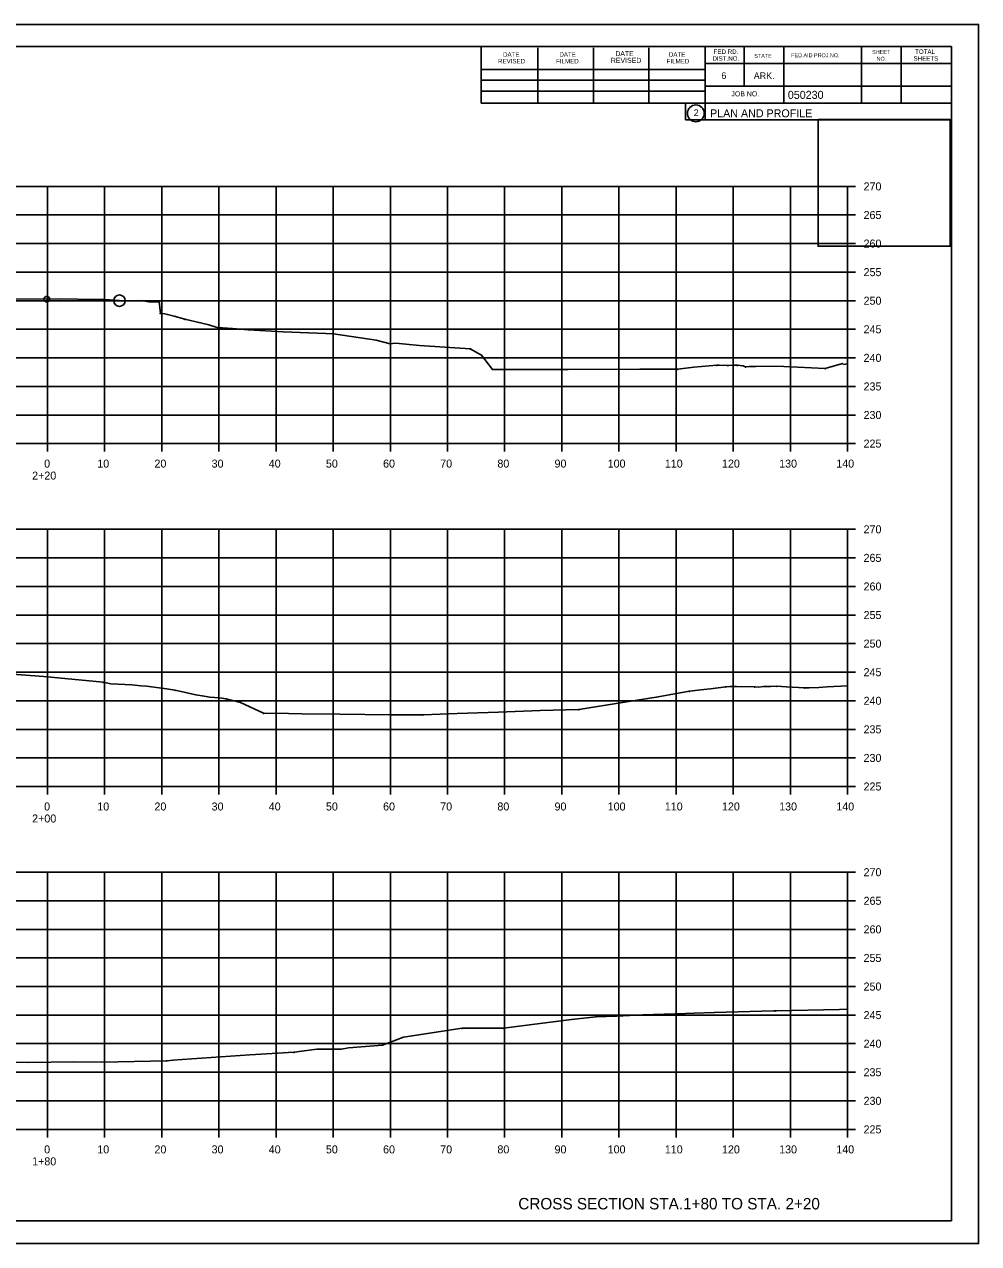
# Model space of a CAD drawing. Extents: x 1300404 to 1323571, y 234004 to 252077.
# Drawn here: x 1315713.3 to 1315880.2, y 240635.1 to 240848.4 of the extents above; entities that cross this region are included whole.
import ezdxf

# ---------------------------------------------------------------- set-up
doc = ezdxf.new("R2010")
doc.units = 0
for name, color, linetype in [('Default', 7, 'Continuous'), ('R_Axis', 7, 'Continuous'), ('R_Axis Annot', 7, 'Continuous'), ('R_Border', 7, 'Continuous'), ('R_Border Prem', 7, 'Continuous'), ('R_Draft', 7, 'Continuous'), ('R_Exist Surface', 7, 'Continuous'), ('R_Grid', 7, 'Continuous'), ('R_No Plot', 7, 'Continuous')]:
    doc.layers.add(name, color=color, linetype=linetype)

msp = doc.modelspace()

# ---------------------------------------------------------------- linework, layer by layer
at = {"layer": 'Default'}
for p, q in [((1315559.28, 240844.54), (1315875.46, 240844.54)), ((1315793.2, 240834.66), (1315793.2, 240844.54)), ((1315803.06, 240834.66), (1315803.06, 240844.34)), ((1315812.82, 240834.66), (1315812.82, 240844.34)), ((1315822.5, 240834.66), (1315822.5, 240844.34)), ((1315832.36, 240844.54), (1315832.36, 240831.74)), ((1315839.2, 240844.54), (1315839.2, 240837.6)), ((1315846.14, 240844.54), (1315846.14, 240834.66)), ((1315859.72, 240844.54), (1315859.72, 240834.66)), ((1315866.66, 240844.54), (1315866.66, 240834.66)), ((1315875.46, 240639.08), (1315875.46, 240844.54)), ((1315875.46, 240841.6), (1315832.36, 240841.6)), ((1315875.46, 240841.62), (1315875.46, 240841.62)), ((1315793.2, 240840.52), (1315832.36, 240840.52)), ((1315793.2, 240838.66), (1315832.36, 240838.66)), ((1315875.46, 240837.6), (1315832.36, 240837.6)), ((1315835.32, 240837.6), (1315875.46, 240837.6)), ((1315793.2, 240834.66), (1315793.2, 240836.72)), ((1315793.2, 240836.72), (1315832.36, 240836.72)), ((1315875.46, 240834.66), (1315793.2, 240834.66)), ((1315832.36, 240831.74), (1315875.46, 240831.74)), ((1315875.46, 240639.08), (1315559.28, 240639.08))]:
    msp.add_line(p, q, dxfattribs=at)
msp.add_circle((1315830.74, 240832.87), 1.47, dxfattribs=at)
at = {"layer": 'R_Axis'}
for p, q in [((1315857.28, 240775.08), (1315857.28, 240820.08)), ((1315858.68, 240820.08), (1315857.28, 240820.08)), ((1315858.68, 240815.08), (1315857.28, 240815.08)), ((1315858.68, 240810.08), (1315857.28, 240810.08)), ((1315858.68, 240805.08), (1315857.28, 240805.08)), ((1315858.68, 240800.08), (1315857.28, 240800.08)), ((1315858.68, 240795.08), (1315857.28, 240795.08)), ((1315858.68, 240790.08), (1315857.28, 240790.08)), ((1315858.68, 240785.08), (1315857.28, 240785.08)), ((1315858.68, 240780.08), (1315857.28, 240780.08)), ((1315577.28, 240775.08), (1315857.28, 240775.08)), ((1315717.28, 240773.68), (1315717.28, 240775.08)), ((1315727.28, 240773.68), (1315727.28, 240775.08)), ((1315737.28, 240773.68), (1315737.28, 240775.08)), ((1315747.28, 240773.68), (1315747.28, 240775.08)), ((1315757.28, 240773.68), (1315757.28, 240775.08)), ((1315767.28, 240773.68), (1315767.28, 240775.08)), ((1315777.28, 240773.68), (1315777.28, 240775.08)), ((1315787.28, 240773.68), (1315787.28, 240775.08)), ((1315797.28, 240773.68), (1315797.28, 240775.08)), ((1315807.28, 240773.68), (1315807.28, 240775.08)), ((1315817.28, 240773.68), (1315817.28, 240775.08)), ((1315827.28, 240773.68), (1315827.28, 240775.08)), ((1315837.28, 240773.68), (1315837.28, 240775.08)), ((1315847.28, 240773.68), (1315847.28, 240775.08)), ((1315857.28, 240773.68), (1315857.28, 240775.08)), ((1315858.68, 240775.08), (1315857.28, 240775.08)), ((1315857.28, 240715.08), (1315857.28, 240760.08)), ((1315858.68, 240760.08), (1315857.28, 240760.08)), ((1315858.68, 240755.08), (1315857.28, 240755.08)), ((1315858.68, 240750.08), (1315857.28, 240750.08)), ((1315858.68, 240745.08), (1315857.28, 240745.08)), ((1315858.68, 240740.08), (1315857.28, 240740.08)), ((1315858.68, 240735.08), (1315857.28, 240735.08)), ((1315858.68, 240730.08), (1315857.28, 240730.08)), ((1315858.68, 240725.08), (1315857.28, 240725.08)), ((1315858.68, 240720.08), (1315857.28, 240720.08)), ((1315577.28, 240715.08), (1315857.28, 240715.08)), ((1315717.28, 240713.68), (1315717.28, 240715.08)), ((1315727.28, 240713.68), (1315727.28, 240715.08)), ((1315737.28, 240713.68), (1315737.28, 240715.08)), ((1315747.28, 240713.68), (1315747.28, 240715.08)), ((1315757.28, 240713.68), (1315757.28, 240715.08)), ((1315767.28, 240713.68), (1315767.28, 240715.08)), ((1315777.28, 240713.68), (1315777.28, 240715.08)), ((1315787.28, 240713.68), (1315787.28, 240715.08)), ((1315797.28, 240713.68), (1315797.28, 240715.08)), ((1315807.28, 240713.68), (1315807.28, 240715.08)), ((1315817.28, 240713.68), (1315817.28, 240715.08)), ((1315827.28, 240713.68), (1315827.28, 240715.08)), ((1315837.28, 240713.68), (1315837.28, 240715.08)), ((1315847.28, 240713.68), (1315847.28, 240715.08)), ((1315857.28, 240713.68), (1315857.28, 240715.08)), ((1315858.68, 240715.08), (1315857.28, 240715.08)), ((1315857.28, 240655.08), (1315857.28, 240700.08)), ((1315858.68, 240700.08), (1315857.28, 240700.08)), ((1315858.68, 240695.08), (1315857.28, 240695.08)), ((1315858.68, 240690.08), (1315857.28, 240690.08)), ((1315858.68, 240685.08), (1315857.28, 240685.08)), ((1315858.68, 240680.08), (1315857.28, 240680.08)), ((1315858.68, 240675.08), (1315857.28, 240675.08)), ((1315858.68, 240670.08), (1315857.28, 240670.08)), ((1315858.68, 240665.08), (1315857.28, 240665.08)), ((1315858.68, 240660.08), (1315857.28, 240660.08)), ((1315577.28, 240655.08), (1315857.28, 240655.08)), ((1315717.28, 240653.68), (1315717.28, 240655.08)), ((1315727.28, 240653.68), (1315727.28, 240655.08)), ((1315737.28, 240653.68), (1315737.28, 240655.08)), ((1315747.28, 240653.68), (1315747.28, 240655.08)), ((1315757.28, 240653.68), (1315757.28, 240655.08)), ((1315767.28, 240653.68), (1315767.28, 240655.08)), ((1315777.28, 240653.68), (1315777.28, 240655.08)), ((1315787.28, 240653.68), (1315787.28, 240655.08)), ((1315797.28, 240653.68), (1315797.28, 240655.08)), ((1315807.28, 240653.68), (1315807.28, 240655.08)), ((1315817.28, 240653.68), (1315817.28, 240655.08)), ((1315827.28, 240653.68), (1315827.28, 240655.08)), ((1315837.28, 240653.68), (1315837.28, 240655.08)), ((1315847.28, 240653.68), (1315847.28, 240655.08)), ((1315857.28, 240653.68), (1315857.28, 240655.08)), ((1315858.68, 240655.08), (1315857.28, 240655.08))]:
    msp.add_line(p, q, dxfattribs=at)
at = {"layer": 'R_Draft'}
for points in [[(1315736.86, 240799.94), (1315736.91, 240799.84), (1315736.81, 240799.84)], [(1315737.04, 240797.94), (1315737.09, 240797.84), (1315736.99, 240797.84)], [(1315741.32, 240796.89), (1315741.37, 240796.79), (1315741.27, 240796.79)], [(1315747.17, 240795.4), (1315747.22, 240795.3), (1315747.12, 240795.3)], [(1315777.24, 240792.6), (1315777.29, 240792.5), (1315777.19, 240792.5)], [(1315791.24, 240791.71), (1315791.29, 240791.61), (1315791.19, 240791.61)], [(1315795.17, 240788.12), (1315795.22, 240788.02), (1315795.12, 240788.02)], [(1315827.59, 240788.15), (1315827.64, 240788.05), (1315827.54, 240788.05)], [(1315834.38, 240788.84), (1315834.43, 240788.74), (1315834.33, 240788.74)], [(1315836.34, 240788.79), (1315836.39, 240788.69), (1315836.29, 240788.69)], [(1315838.01, 240788.84), (1315838.06, 240788.74), (1315837.96, 240788.74)], [(1315839.43, 240788.57), (1315839.48, 240788.47), (1315839.38, 240788.47)], [(1315853.38, 240788.27), (1315853.43, 240788.17), (1315853.33, 240788.17)], [(1315727.06, 240733.36), (1315727.11, 240733.26), (1315727.01, 240733.26)], [(1315835.97, 240732.57), (1315836.02, 240732.47), (1315835.92, 240732.47)], [(1315840.99, 240732.57), (1315841.04, 240732.47), (1315840.94, 240732.47)], [(1315844.88, 240732.68), (1315844.93, 240732.58), (1315844.83, 240732.58)], [(1315849.72, 240732.4), (1315849.77, 240732.3), (1315849.67, 240732.3)], [(1315739.61, 240732), (1315739.66, 240731.9), (1315739.56, 240731.9)], [(1315748.56, 240730.47), (1315748.61, 240730.37), (1315748.51, 240730.37)], [(1315829.62, 240731.82), (1315829.67, 240731.72), (1315829.57, 240731.72)], [(1315810.28, 240728.61), (1315810.33, 240728.51), (1315810.23, 240728.51)], [(1315755.09, 240727.97), (1315755.14, 240727.87), (1315755.04, 240727.87)], [(1315783, 240727.66), (1315783.05, 240727.56), (1315782.95, 240727.56)], [(1315813.23, 240674.85), (1315813.28, 240674.75), (1315813.18, 240674.75)], [(1315833.98, 240675.61), (1315834.03, 240675.51), (1315833.93, 240675.51)], [(1315844.72, 240675.87), (1315844.77, 240675.77), (1315844.67, 240675.77)], [(1315789.82, 240672.82), (1315789.87, 240672.72), (1315789.77, 240672.72)], [(1315797.1, 240672.86), (1315797.15, 240672.76), (1315797.05, 240672.76)], [(1315760.44, 240668.63), (1315760.49, 240668.53), (1315760.39, 240668.53)], [(1315738.15, 240667.13), (1315738.2, 240667.03), (1315738.1, 240667.03)]]:
    msp.add_lwpolyline(points, close=True, dxfattribs=at)
at = {"layer": 'R_Exist Surface'}
for points in [[(1315711.59, 240800.38), (1315717.17, 240800.33), (1315719.63, 240800.41), (1315725.48, 240800.31), (1315727.26, 240800.27), (1315729.88, 240800.09), (1315730.83, 240800.05), (1315730.89, 240800.05), (1315731.2, 240800.05), (1315733.66, 240800.09), (1315735, 240799.9), (1315736.23, 240799.9), (1315736.43, 240799.9), (1315736.86, 240799.89), (1315736.99, 240798.37), (1315737.04, 240797.89), (1315737.83, 240797.76), (1315739.48, 240797.38), (1315741.32, 240796.84), (1315745.54, 240795.84), (1315747.17, 240795.35), (1315747.93, 240795.33), (1315749.67, 240795.24), (1315752.42, 240794.96), (1315758.55, 240794.66), (1315766.01, 240794.34), (1315767.36, 240794.3), (1315774.83, 240793.19), (1315777.24, 240792.55), (1315778.09, 240792.65), (1315778.85, 240792.6), (1315780.02, 240792.5), (1315782.41, 240792.27), (1315791.24, 240791.66), (1315793.25, 240790.56), (1315795.17, 240788.07), (1315803.81, 240788.02), (1315808.37, 240788.03), (1315820.92, 240788.08), (1315824.99, 240788.08), (1315827.59, 240788.1), (1315830.36, 240788.48), (1315834.38, 240788.79), (1315834.83, 240788.79), (1315836.34, 240788.74), (1315837.48, 240788.8), (1315838.01, 240788.79), (1315838.97, 240788.68), (1315839.43, 240788.52), (1315840.04, 240788.57), (1315841.21, 240788.58), (1315843.87, 240788.6), (1315846.11, 240788.54), (1315848.59, 240788.44), (1315853.38, 240788.22), (1315856.37, 240789.12), (1315856.58, 240788.93), (1315857.28, 240789.02)], [(1315707.92, 240734.96), (1315716.68, 240734.32), (1315727.06, 240733.31), (1315728.4, 240733.06), (1315732.08, 240732.87), (1315733.61, 240732.72), (1315734.63, 240732.63), (1315737.73, 240732.21), (1315739.61, 240731.95), (1315743.23, 240731.1), (1315744.73, 240730.88), (1315745.69, 240730.69), (1315747.4, 240730.59), (1315748.56, 240730.42), (1315749.96, 240730.08), (1315751.09, 240729.8), (1315755.09, 240727.92), (1315759.49, 240727.83), (1315761.87, 240727.8), (1315768.44, 240727.74), (1315777.26, 240727.63), (1315783, 240727.61), (1315788.97, 240727.88), (1315796.22, 240728.11), (1315803.49, 240728.39), (1315810.28, 240728.56), (1315818.24, 240729.82), (1315823.8, 240730.7), (1315829.62, 240731.77), (1315832.11, 240732.06), (1315833.31, 240732.17), (1315835.97, 240732.52), (1315836.67, 240732.58), (1315837.85, 240732.57), (1315840.99, 240732.52), (1315841.7, 240732.48), (1315842.6, 240732.55), (1315843.78, 240732.57), (1315844.88, 240732.63), (1315846.55, 240732.5), (1315849.72, 240732.35), (1315850.02, 240732.36), (1315850.55, 240732.36), (1315852.27, 240732.43), (1315853.71, 240732.52), (1315857.28, 240732.67)], [(1315704.52, 240666.92), (1315713.95, 240666.79), (1315721.83, 240666.88), (1315726.82, 240666.84), (1315738.15, 240667.08), (1315739.3, 240667.2), (1315740.87, 240667.3), (1315752.71, 240668.15), (1315760.44, 240668.58), (1315764.43, 240669.09), (1315768.74, 240669.12), (1315769.98, 240669.35), (1315775.89, 240669.83), (1315779.58, 240671.24), (1315789.82, 240672.77), (1315793.4, 240672.77), (1315795.31, 240672.77), (1315797.1, 240672.81), (1315808.99, 240674.31), (1315813.23, 240674.8), (1315816.88, 240674.91), (1315821.45, 240675.11), (1315828.93, 240675.33), (1315830.45, 240675.44), (1315833.98, 240675.56), (1315844.32, 240675.82), (1315844.6, 240675.82), (1315844.72, 240675.82), (1315855.88, 240676.06), (1315857.28, 240676.11)]]:
    msp.add_lwpolyline(points, dxfattribs=at)
at = {"layer": 'R_Grid'}
for p, q in [((1315577.28, 240820.08), (1315857.28, 240820.08)), ((1315717.28, 240775.08), (1315717.28, 240820.08)), ((1315727.28, 240775.08), (1315727.28, 240820.08)), ((1315737.28, 240775.08), (1315737.28, 240820.08)), ((1315747.28, 240775.08), (1315747.28, 240820.08)), ((1315757.28, 240775.08), (1315757.28, 240820.08)), ((1315767.28, 240775.08), (1315767.28, 240820.08)), ((1315777.28, 240775.08), (1315777.28, 240820.08)), ((1315787.28, 240775.08), (1315787.28, 240820.08)), ((1315797.28, 240775.08), (1315797.28, 240820.08)), ((1315807.28, 240775.08), (1315807.28, 240820.08)), ((1315817.28, 240775.08), (1315817.28, 240820.08)), ((1315827.28, 240775.08), (1315827.28, 240820.08)), ((1315837.28, 240775.08), (1315837.28, 240820.08)), ((1315847.28, 240775.08), (1315847.28, 240820.08)), ((1315857.28, 240775.08), (1315857.28, 240820.08)), ((1315577.28, 240815.08), (1315857.28, 240815.08)), ((1315577.28, 240810.08), (1315857.28, 240810.08)), ((1315577.28, 240805.08), (1315857.28, 240805.08)), ((1315577.28, 240800.08), (1315857.28, 240800.08)), ((1315577.28, 240795.08), (1315857.28, 240795.08)), ((1315577.28, 240790.08), (1315857.28, 240790.08)), ((1315577.28, 240785.08), (1315857.28, 240785.08)), ((1315577.28, 240780.08), (1315857.28, 240780.08)), ((1315577.28, 240775.08), (1315857.28, 240775.08)), ((1315577.28, 240760.08), (1315857.28, 240760.08)), ((1315717.28, 240715.08), (1315717.28, 240760.08)), ((1315727.28, 240715.08), (1315727.28, 240760.08)), ((1315737.28, 240715.08), (1315737.28, 240760.08)), ((1315747.28, 240715.08), (1315747.28, 240760.08)), ((1315757.28, 240715.08), (1315757.28, 240760.08)), ((1315767.28, 240715.08), (1315767.28, 240760.08)), ((1315777.28, 240715.08), (1315777.28, 240760.08)), ((1315787.28, 240715.08), (1315787.28, 240760.08)), ((1315797.28, 240715.08), (1315797.28, 240760.08)), ((1315807.28, 240715.08), (1315807.28, 240760.08)), ((1315817.28, 240715.08), (1315817.28, 240760.08)), ((1315827.28, 240715.08), (1315827.28, 240760.08)), ((1315837.28, 240715.08), (1315837.28, 240760.08)), ((1315847.28, 240715.08), (1315847.28, 240760.08)), ((1315857.28, 240715.08), (1315857.28, 240760.08)), ((1315577.28, 240755.08), (1315857.28, 240755.08)), ((1315577.28, 240750.08), (1315857.28, 240750.08)), ((1315577.28, 240745.08), (1315857.28, 240745.08)), ((1315577.28, 240740.08), (1315857.28, 240740.08)), ((1315577.28, 240735.08), (1315857.28, 240735.08)), ((1315577.28, 240730.08), (1315857.28, 240730.08)), ((1315577.28, 240725.08), (1315857.28, 240725.08)), ((1315577.28, 240720.08), (1315857.28, 240720.08)), ((1315577.28, 240715.08), (1315857.28, 240715.08)), ((1315577.28, 240700.08), (1315857.28, 240700.08)), ((1315717.28, 240655.08), (1315717.28, 240700.08)), ((1315727.28, 240655.08), (1315727.28, 240700.08)), ((1315737.28, 240655.08), (1315737.28, 240700.08)), ((1315747.28, 240655.08), (1315747.28, 240700.08)), ((1315757.28, 240655.08), (1315757.28, 240700.08)), ((1315767.28, 240655.08), (1315767.28, 240700.08)), ((1315777.28, 240655.08), (1315777.28, 240700.08)), ((1315787.28, 240655.08), (1315787.28, 240700.08)), ((1315797.28, 240655.08), (1315797.28, 240700.08)), ((1315807.28, 240655.08), (1315807.28, 240700.08)), ((1315817.28, 240655.08), (1315817.28, 240700.08)), ((1315827.28, 240655.08), (1315827.28, 240700.08)), ((1315837.28, 240655.08), (1315837.28, 240700.08)), ((1315847.28, 240655.08), (1315847.28, 240700.08)), ((1315857.28, 240655.08), (1315857.28, 240700.08)), ((1315577.28, 240695.08), (1315857.28, 240695.08)), ((1315577.28, 240690.08), (1315857.28, 240690.08)), ((1315577.28, 240685.08), (1315857.28, 240685.08)), ((1315577.28, 240680.08), (1315857.28, 240680.08)), ((1315577.28, 240675.08), (1315857.28, 240675.08)), ((1315577.28, 240670.08), (1315857.28, 240670.08)), ((1315577.28, 240665.08), (1315857.28, 240665.08)), ((1315577.28, 240660.08), (1315857.28, 240660.08)), ((1315577.28, 240655.08), (1315857.28, 240655.08))]:
    msp.add_line(p, q, dxfattribs=at)
at = {"layer": 'R_No Plot'}
for p, q in [((1315546.87, 240848.43), (1315880.21, 240848.43)), ((1315546.87, 240635.1), (1315880.21, 240635.1))]:
    msp.add_line(p, q, dxfattribs=at)
for points in [[(1315546.87, 240848.43), (1315880.21, 240848.43), (1315880.21, 240635.09), (1315546.87, 240635.09)], [(1315793.2, 240844.54), (1315793.2, 240834.66), (1315828.93, 240834.66), (1315828.93, 240831.74), (1315852.13, 240831.74), (1315852.13, 240809.62), (1315875.46, 240809.62), (1315875.46, 240639.08), (1315559.28, 240639.08), (1315559.28, 240844.54)], [(1315852.13, 240831.77), (1315875.23, 240831.77), (1315875.23, 240809.62), (1315852.13, 240809.62)]]:
    msp.add_lwpolyline(points, close=True, dxfattribs=at)
for centre, radius in [((1315717.17, 240800.33), 0.5), ((1315729.88, 240800.09), 1)]:
    msp.add_circle(centre, radius, dxfattribs=at)

# ---------------------------------------------------------------- texts
at = {"layer": 'Default'}
msp.add_text('2', height=1.17, dxfattribs=at).set_placement((1315830.36, 240832.39))
at = {"layer": 'R_Axis Annot'}
for s, p in [('270', (1315860.08, 240819.38)), ('265', (1315860.08, 240814.38)), ('260', (1315860.08, 240809.38)), ('255', (1315860.08, 240804.38)), ('250', (1315860.08, 240799.38)), ('245', (1315860.08, 240794.38)), ('240', (1315860.08, 240789.38)), ('235', (1315860.08, 240784.38)), ('230', (1315860.08, 240779.38)), ('225', (1315860.08, 240774.38)), ('0', (1315716.71, 240770.88)), ('10', (1315726.01, 240770.88)), ('20', (1315736.01, 240770.88)), ('30', (1315746.01, 240770.88)), ('40', (1315756.01, 240770.88)), ('50', (1315766.01, 240770.88)), ('60', (1315776.01, 240770.88)), ('70', (1315786.01, 240770.88)), ('80', (1315796.01, 240770.88)), ('90', (1315806.01, 240770.88)), ('100', (1315815.31, 240770.88)), ('110', (1315825.31, 240770.88)), ('120', (1315835.31, 240770.88)), ('130', (1315845.31, 240770.88)), ('140', (1315855.31, 240770.88)), ('2+20', (1315714.61, 240768.78)), ('270', (1315860.08, 240759.38)), ('265', (1315860.08, 240754.38)), ('260', (1315860.08, 240749.38)), ('255', (1315860.08, 240744.38)), ('250', (1315860.08, 240739.38)), ('245', (1315860.08, 240734.38)), ('240', (1315860.08, 240729.38)), ('235', (1315860.08, 240724.38)), ('230', (1315860.08, 240719.38)), ('225', (1315860.08, 240714.38)), ('0', (1315716.71, 240710.88)), ('10', (1315726.01, 240710.88)), ('20', (1315736.01, 240710.88)), ('30', (1315746.01, 240710.88)), ('40', (1315756.01, 240710.88)), ('50', (1315766.01, 240710.88)), ('60', (1315776.01, 240710.88)), ('70', (1315786.01, 240710.88)), ('80', (1315796.01, 240710.88)), ('90', (1315806.01, 240710.88)), ('100', (1315815.31, 240710.88)), ('110', (1315825.31, 240710.88)), ('120', (1315835.31, 240710.88)), ('130', (1315845.31, 240710.88)), ('140', (1315855.31, 240710.88)), ('2+00', (1315714.61, 240708.78)), ('270', (1315860.08, 240699.38)), ('265', (1315860.08, 240694.38)), ('260', (1315860.08, 240689.38)), ('255', (1315860.08, 240684.38)), ('250', (1315860.08, 240679.38)), ('245', (1315860.08, 240674.38)), ('240', (1315860.08, 240669.38)), ('235', (1315860.08, 240664.38)), ('230', (1315860.08, 240659.38)), ('225', (1315860.08, 240654.38)), ('0', (1315716.71, 240650.88)), ('10', (1315726.01, 240650.88)), ('20', (1315736.01, 240650.88)), ('30', (1315746.01, 240650.88)), ('40', (1315756.01, 240650.88)), ('50', (1315766.01, 240650.88)), ('60', (1315776.01, 240650.88)), ('70', (1315786.01, 240650.88)), ('80', (1315796.01, 240650.88)), ('90', (1315806.01, 240650.88)), ('100', (1315815.31, 240650.88)), ('110', (1315825.31, 240650.88)), ('120', (1315835.31, 240650.88)), ('130', (1315845.31, 240650.88)), ('140', (1315855.31, 240650.88)), ('1+80', (1315714.61, 240648.78))]:
    msp.add_text(s, height=1.4, dxfattribs=at).set_placement(p)
at = {"layer": 'R_Border'}
for s, height, p in [('DATE', 0.782, (1315797, 240842.78)), ('DATE', 0.782, (1315806.86, 240842.78)), ('DATE', 0.879, (1315816.64, 240842.88)), ('DATE', 0.782, (1315826.02, 240842.78)), ('FED.RD.', 0.782, (1315833.84, 240843.26)), ('STATE', 0.684, (1315840.96, 240842.58)), ('FED.AID PROJ.NO.', 0.684, (1315847.42, 240842.68)), ('SHEET', 0.684, (1315861.58, 240843.26)), ('TOTAL', 0.782, (1315869.1, 240843.26)), ('REVISED', 0.782, (1315796.12, 240841.6)), ('FILMED', 0.782, (1315806.28, 240841.6)), ('REVISED', 0.879, (1315815.86, 240841.7)), ('FILMED', 0.782, (1315825.62, 240841.6)), ('DIST.NO.', 0.782, (1315833.64, 240842.08)), ('NO.', 0.684, (1315862.36, 240842.08)), ('SHEETS', 0.782, (1315868.82, 240842.08)), ('6', 1.17, (1315835.2, 240838.86)), ('ARK.', 1.172, (1315840.86, 240838.86)), ('JOB NO.', 0.879, (1315836.96, 240835.84))]:
    msp.add_text(s, height=height, dxfattribs=at).set_placement(p)
for s, p in [('050230', (1315846.83, 240835.4)), ('PLAN AND PROFILE', (1315833.22, 240832.17))]:
    msp.add_text(s, height=1.4, rotation=360, dxfattribs=at).set_placement(p)
at = {"layer": 'R_Border Prem'}
msp.add_text('DWB', height=0.01, dxfattribs=at).set_placement((1315836.15, 240826.05))
at = {"layer": 'R_Draft'}
msp.add_text('CROSS SECTION STA.1+80 TO STA. 2+20', height=2, dxfattribs=at).set_placement((1315799.67, 240641.08))

doc.saveas('drawing.dxf')
